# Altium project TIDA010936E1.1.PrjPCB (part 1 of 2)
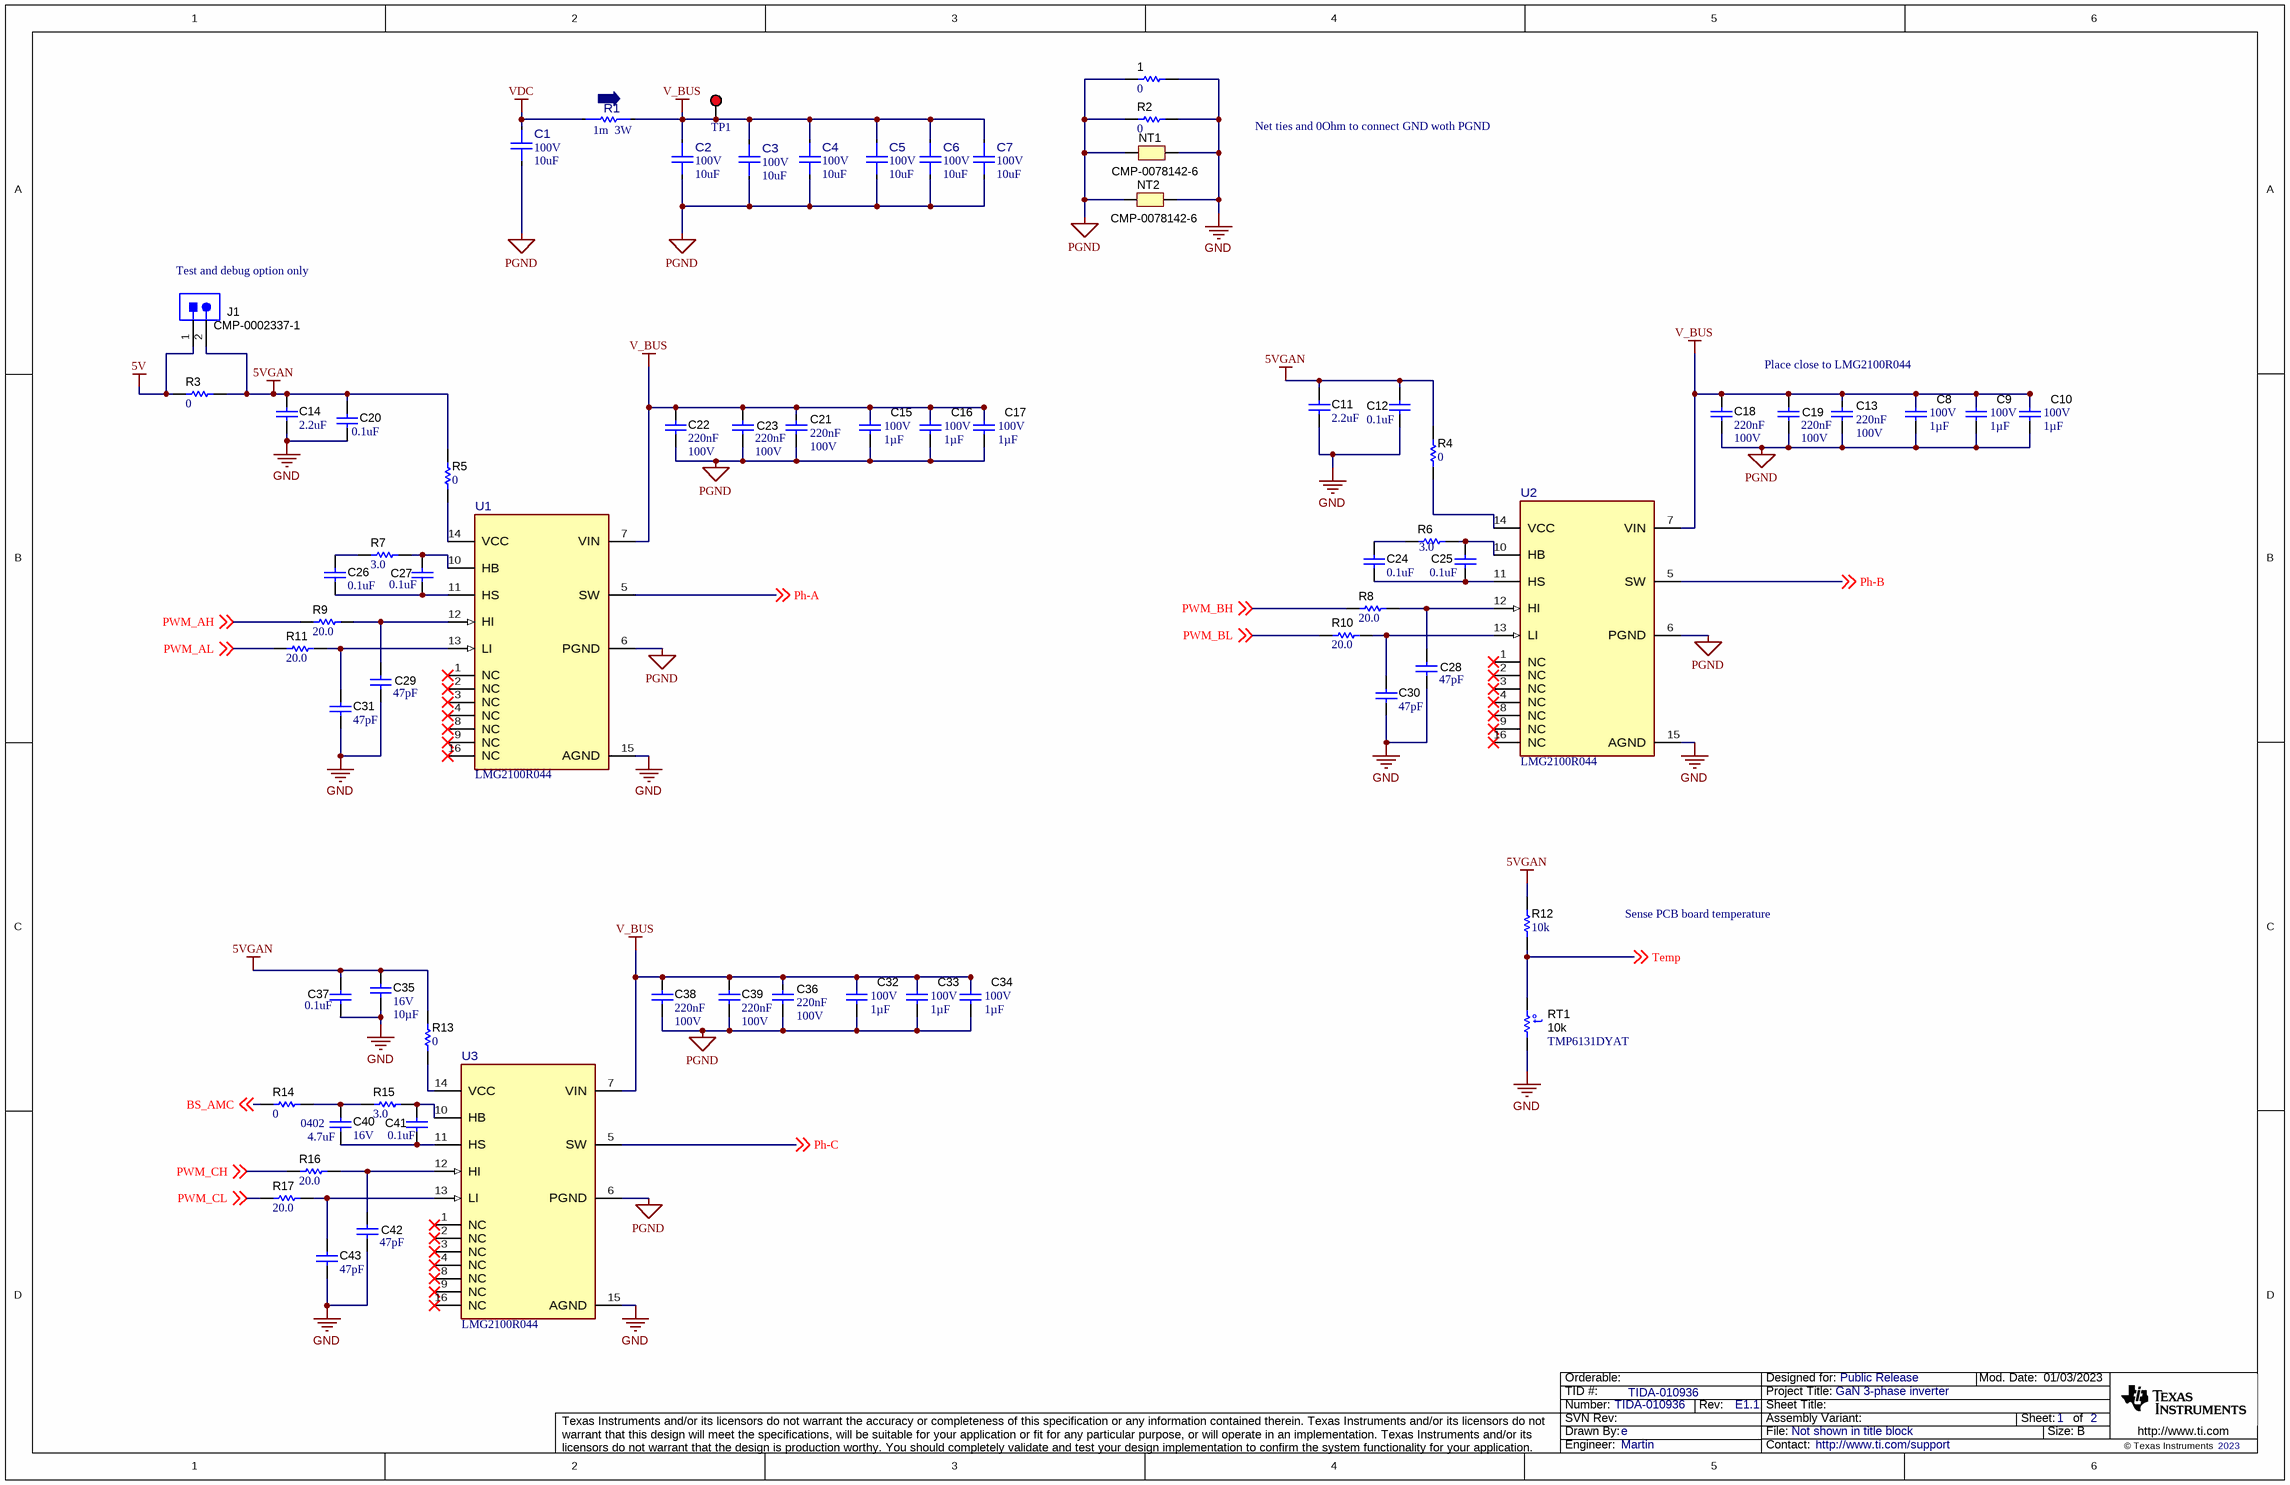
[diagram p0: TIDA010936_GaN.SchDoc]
CopyrightYear: 2023; PCB_Layout: Eason; PCB_Rev: E1.1; PRJ_Customer: Public Release; PRJ_Engineer: Martin; PRJ_Number: TIDA-010936; PRJ_Title: GaN 3-phase inverter; SCH_Rev: E1.1; TechSupport: http://www.ti.com/support; TID: TIDA-010936
5 sheets, 225 parts. Net scope: global (net labels, ports and power ports of the same name join across sheets).
Board file: TIDA010936.PcbDoc
Sheets:
  TIDA010936_GaN.SchDoc
  TIDA010936_Current sensing.SchDoc
  TIDA010936_Interface.SchDoc
  TIDA010936_Power.SchDoc
  TIDA010936_GaN_Hardware.SchDoc

## Sheet TIDA010936_GaN.SchDoc
size 431 x 279 mm; Date: Not shown in title block; ApprovedBy: Not shown in title block; CheckedBy: Not shown in title block; Author: Not shown in title block; CompanyName: Not shown in title block; DrawnBy: e; Engineer: Not shown in title block; Organization: Not shown in title block; Address1: Not shown in title block; Address2: Not shown in title block; Address3: Not shown in title block; Address4: Not shown in title block; DocumentNumber: 2; Revision: Use project parameter SCH_Rev; SheetNumber: 1; SheetTotal: 2; PageSetup: Record=PageOptions¦CenterHorizontal=True¦CenterVertical=True¦PrintScale=1.00¦XCorrection=1.00¦YCorrection=1.00¦PrintKind=0¦BorderSize=5000000¦LeftOffset=0¦BottomOffset=0¦Orientation=2¦PaperLength=1000¦PaperWidth=1000¦Scale=100¦PaperSource=15¦PrintQuality=600¦MediaType=1¦DitherType=10¦PaperKind=Letter¦PrintScaleMode=1

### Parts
1  ValueDisplayed: 0  [0603]  (hidden comment: CMP-0025883-3)
C1  VDC_V: 100V  ValueDisplayed: 10uF  [FP-C3225X7R2A106K250AC_1210-MFG]  (hidden comment: C3225X7R2A106K250AC)
C2  VDC_V: 100V  ValueDisplayed: 10uF  [FP-C3225X7R2A106K250AC_1210-MFG]  (hidden comment: C3225X7R2A106K250AC)
C3  VDC_V: 100V  ValueDisplayed: 10uF  [FP-C3225X7R2A106K250AC_1210-MFG]  (hidden comment: C3225X7R2A106K250AC)
C4  VDC_V: 100V  ValueDisplayed: 10uF  [FP-C3225X7R2A106K250AC_1210-MFG]  (hidden comment: C3225X7R2A106K250AC)
C5  VDC_V: 100V  ValueDisplayed: 10uF  [FP-C3225X7R2A106K250AC_1210-MFG]  (hidden comment: C3225X7R2A106K250AC)
C6  VDC_V: 100V  ValueDisplayed: 10uF  [FP-C3225X7R2A106K250AC_1210-MFG]  (hidden comment: C3225X7R2A106K250AC)
C7  VDC_V: 100V  ValueDisplayed: 10uF  [FP-C3225X7R2A106K250AC_1210-MFG]  (hidden comment: C3225X7R2A106K250AC)
C8  VDC_V: 100V  ValueDisplayed: 1µF  [0805_HV]  (hidden comment: C2012X7S2A105K125AE)
C9  VDC_V: 100V  ValueDisplayed: 1µF  [0805_HV]  (hidden comment: C2012X7S2A105K125AE)
C10  VDC_V: 100V  ValueDisplayed: 1µF  [0805_HV]  (hidden comment: C2012X7S2A105K125AE)
C11  ValueDisplayed: 2.2uF  [0402_065]  (hidden comment: C1005X7S1A225K050BC)
C12  ValueDisplayed: 0.1uF  [0402]  (hidden comment: CMP-0006351-2)
C13  Cap_F: 220nF  VDC_V: 100V  [0603]  (hidden comment: HMK107C7224KAHTE)
C14  ValueDisplayed: 2.2uF  [0402_065]  (hidden comment: C1005X7S1A225K050BC)
C15  VDC_V: 100V  ValueDisplayed: 1µF  [0805_HV]  (hidden comment: C2012X7S2A105K125AE)
C16  VDC_V: 100V  ValueDisplayed: 1µF  [0805_HV]  (hidden comment: C2012X7S2A105K125AE)
C17  VDC_V: 100V  ValueDisplayed: 1µF  [0805_HV]  (hidden comment: C2012X7S2A105K125AE)
C18  Cap_F: 220nF  VDC_V: 100V  [0603]  (hidden comment: HMK107C7224KAHTE)
C19  Cap_F: 220nF  VDC_V: 100V  [0603]  (hidden comment: HMK107C7224KAHTE)
C20  ValueDisplayed: 0.1uF  [0402]  (hidden comment: CMP-0006351-2)
C21  Cap_F: 220nF  VDC_V: 100V  [0603]  (hidden comment: HMK107C7224KAHTE)
C22  Cap_F: 220nF  VDC_V: 100V  [0603]  (hidden comment: HMK107C7224KAHTE)
C23  Cap_F: 220nF  VDC_V: 100V  [0603]  (hidden comment: HMK107C7224KAHTE)
C24  ValueDisplayed: 0.1uF  [0402]  (hidden comment: CMP-0006351-2)
C25  ValueDisplayed: 0.1uF  [0402]  (hidden comment: CMP-0006351-2)
C26  ValueDisplayed: 0.1uF  [0402]  (hidden comment: CMP-0006351-2)
C27  ValueDisplayed: 0.1uF  [0402]  (hidden comment: CMP-0006351-2)
C28  ValueDisplayed: 47pF  [0402]  (hidden comment: CMP-0006388-2)
C29  ValueDisplayed: 47pF  [0402]  (hidden comment: CMP-0006388-2)
C30  ValueDisplayed: 47pF  [0402]  (hidden comment: CMP-0006388-2)
C31  ValueDisplayed: 47pF  [0402]  (hidden comment: CMP-0006388-2)
C32  VDC_V: 100V  ValueDisplayed: 1µF  [0805_HV]  (hidden comment: C2012X7S2A105K125AE)
C33  VDC_V: 100V  ValueDisplayed: 1µF  [0805_HV]  (hidden comment: C2012X7S2A105K125AE)
C34  VDC_V: 100V  ValueDisplayed: 1µF  [0805_HV]  (hidden comment: C2012X7S2A105K125AE)
C35  VDC_V: 16V  ValueDisplayed: 10µF  [0603]  (hidden comment: GRM188C81C106MA73D)
C36  Cap_F: 220nF  VDC_V: 100V  [0603]  (hidden comment: HMK107C7224KAHTE)
C37  ValueDisplayed: 0.1uF  [0402]  (hidden comment: CMP-0006351-2)
C38  Cap_F: 220nF  VDC_V: 100V  [0603]  (hidden comment: HMK107C7224KAHTE)
C39  Cap_F: 220nF  VDC_V: 100V  [0603]  (hidden comment: HMK107C7224KAHTE)
C40  PackageReference: 0402  VDC_V: 16V  ValueDisplayed: 4.7uF  [0402_070]  (hidden comment: GRM155D81C475ME15D)
C41  ValueDisplayed: 0.1uF  [0402]  (hidden comment: CMP-0006351-2)
C42  ValueDisplayed: 47pF  [0402]  (hidden comment: CMP-0006388-2)
C43  ValueDisplayed: 47pF  [0402]  (hidden comment: CMP-0006388-2)
J1  CMP-0002337-1  [CONN_PEC02SAAN]
NT1  CMP-0078142-6  [Net-Tie_50milWide_30milLong]  (net tie, no BOM)
NT2  CMP-0078142-6  [Net-Tie_50milWide_30milLong]  (net tie, no BOM)
R1  value 1m  Power_W: 3W  [FP-ULRG32512R001FLFSLT_2512-MFG]  (hidden comment: ULRG32512R001FLFSLT)
R2  ValueDisplayed: 0  [0603]  (hidden comment: CMP-0025883-3)
R3  ValueDisplayed: 0  [0402]  (hidden comment: CMP-0026822-3)
R4  ValueDisplayed: 0  [0402]  (hidden comment: CMP-0026822-3)
R5  ValueDisplayed: 0  [0402]  (hidden comment: CMP-0026822-3)
R6  ValueDisplayed: 3.0  [0402]  (hidden comment: CRCW04023R00JNED)
R7  ValueDisplayed: 3.0  [0402]  (hidden comment: CRCW04023R00JNED)
R8  ValueDisplayed: 20.0  [0402]  (hidden comment: CMP-0026164-2)
R9  ValueDisplayed: 20.0  [0402]  (hidden comment: CMP-0026164-2)
R10  ValueDisplayed: 20.0  [0402]  (hidden comment: CMP-0026164-2)
R11  ValueDisplayed: 20.0  [0402]  (hidden comment: CMP-0026164-2)
R12  ValueDisplayed: 10k  [0402]  (hidden comment: CMP-0026825-5)
R13  ValueDisplayed: 0  [0402]  (hidden comment: CMP-0026822-3)
R14  ValueDisplayed: 0  [0402]  (hidden comment: CMP-0026822-3)
R15  ValueDisplayed: 3.0  [0402]  (hidden comment: CRCW04023R00JNED)
R16  ValueDisplayed: 20.0  [0402]  (hidden comment: CMP-0026164-2)
R17  ValueDisplayed: 20.0  [0402]  (hidden comment: CMP-0026164-2)
RT1  value 10k  [DYA0002A-MFG]  (hidden comment: TMP6131DYAT)
TP1  5000  [Keystone5000]  (value not drawn)
U1  LMG2100R044  [RAR0016A-MFG]
U2  LMG2100R044  [RAR0016A-MFG]
U3  LMG2100R044  [RAR0016A-MFG]

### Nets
5V: J1.1 R3.1
5VGAN: C11.1 C12.2 C14.1 C20.1 C35.1 C37.2 J1.2 R3.2 R4.2 R5.2 R12.2 R13.2
GND: 1.2 C11.2 C12.1 C14.2 C20.2 C28.2 C29.2 C30.2 C31.2 C35.2 C37.1 C42.2 C43.2 NT1.2 NT2.2 R2.2 RT1.1 U1.15(AGND) U2.15(AGND) U3.15(AGND)
PGND: 1.1 C1.2 C2.2 C3.1 C4.2 C5.2 C6.2 C7.2 C8.2 C9.2 C10.2 C13.2 C15.2 C16.2 C17.2 C18.2 C19.2 C21.2 C22.2 C23.2 C32.2 C33.2 C34.2 C36.2 C38.2 C39.2 NT1.1 NT2.1 R2.1 U1.6(PGND) U2.6(PGND) U3.6(PGND)
Ph-A: U1.5(SW) ; off-sheet Ph-A  [project net AIN+]
Ph-B: U2.5(SW) ; off-sheet Ph-B  [project net BIN+]
Ph-C: U3.5(SW) ; off-sheet Ph-C  [project net AMC_GND]
V_BUS: C2.1 C3.2 C4.1 C5.1 C6.1 C7.1 C8.1 C9.1 C10.1 C13.1 C15.1 C16.1 C17.1 C18.1 C19.1 C21.1 C22.1 C23.1 C32.1 C33.1 C34.1 C36.1 C38.1 C39.1 R1.2 TP1.1 U1.7(VIN) U2.7(VIN) U3.7(VIN)
VDC: C1.1 R1.1
BS_AMC: R14.2 ; off-sheet BS_AMC
PWM_AH: R9.2 ; off-sheet PWM_AH
PWM_AL: R11.2 ; off-sheet PWM_AL
PWM_BH: R8.2 ; off-sheet PWM_BH
PWM_BL: R10.2 ; off-sheet PWM_BL
PWM_CH: R16.2 ; off-sheet PWM_CH
PWM_CL: R17.2 ; off-sheet PWM_CL
Temp: R12.1 RT1.2 ; off-sheet Temp
NetC24_1: C24.1 R6.1
NetC24_2: C24.2 C25.2 U2.11(HS)
NetC25_1: C25.1 R6.2 U2.10(HB)
NetC26_1: C26.1 R7.1
NetC26_2: C26.2 C27.2 U1.11(HS)
NetC27_1: C27.1 R7.2 U1.10(HB)
NetC28_1: C28.1 R8.1 U2.12(HI)
NetC29_1: C29.1 R9.1 U1.12(HI)
NetC30_1: C30.1 R10.1 U2.13(LI)
NetC31_1: C31.1 R11.1 U1.13(LI)
NetC40_1: C40.1 R14.1 R15.1
NetC40_2: C40.2 C41.2 U3.11(HS)
NetC41_1: C41.1 R15.2 U3.10(HB)
NetC42_1: C42.1 R16.1 U3.12(HI)
NetC43_1: C43.1 R17.1 U3.13(LI)
NetR4_1: R4.1 U2.14(VCC)
NetR5_1: R5.1 U1.14(VCC)
NetR13_1: R13.1 U3.14(VCC)

Not connected (* = marked no-connect by the designer): U1 1(NC)* 2(NC)* 3(NC)* 4(NC)* 8(NC)* 9(NC)* 16(NC)*; U2 1(NC)* 2(NC)* 3(NC)* 4(NC)* 8(NC)* 9(NC)* 16(NC)*; U3 1(NC)* 2(NC)* 3(NC)* 4(NC)* 8(NC)* 9(NC)* 16(NC)*

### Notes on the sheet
- (near R1) ⬅
- Net ties and 0Ohm to connect GND woth PGND
- (near J1) Test and debug option only
- Place close to LMG2100R044
- Sense PCB board temperature

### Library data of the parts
1 R2 = CMP-0025883-3: RES, 0, 5%, 0.1 W, 0603; PartNumber: MCR03EZPJ000; Manufacturer: Rohm; Value: 0; Value_Code: 0000; Power_W: 100mW; Value2: 0.1W; VDC_V: 50V; TempCo: 400 ppm/C; SizeArea_mm2: 1.28; SizeX_mm: 1.6; SizeY_mm: 0.8; SizeZ_mm: 1; EIA_Code: E24; U/M: EA; AEC Category: Q200; AEC Qualified: N
C1-C7 = CMP-0096021-1: 10 µF ±10% 100V Ceramic Capacitor X7R 1210 (3225 Metric); Manufacturer: TDK; Cap_F: 10µF; AEC Qualified: No; Value: 10µF; SizeZ_mm: 2.85mm; TempCo: 15%
C8-C10 C15-C17 C32-C34 = CMP-0750059-1: CAP, CERM, 1 µF, 100 V,+/- 10%, X7S, 0805; Manufacturer: TDK; TaMax_C: 125°C; SizeAreaWB_mm2: 6.75; SizeY_mm: 1.25; Green_REACh: Incomplete; TaMin_C: -55°C; Cap_Case: 0805; SizeZ_mm: 1.45; U/M: EA; SizeX_mm: 2; Polarized: N; Green_Lifecycle: Active; SizeArea_mm2: 2.5; Value: 1uF; AEC Category: Q200
C11 C14 = CMP-0006302-2: CAP, CERM, 2.2 uF, 10 V, +/- 10%, X7S, 0402; Manufacturer: TDK; Polarized: N; Value: 2.2uF; U/M: EA; Cap_F: 2.2µF; ESR_ohm: 5.925m; Value1: 0.005925 ohm; VDC_V: 10V; IRMS_A: 2.0559A; TaMin_C: -55°C; TaMax_C: 125°C; SizeArea_mm2: 0.5; SizeAreaWB_mm2: 3; SizeX_mm: 1; SizeZ_mm: 0.65; AEC Category: Q200
C12 C20 C24-C27 C37 C41 = CMP-0006351-2: CAP, CERM, 0.1 uF, 16 V, +/- 10%, X7R, 0402; PartNumber: GCM155R71C104KA55D; Manufacturer: MuRata; Polarized: N; Value: 0.1uF; U/M: EA; Cap_F: 100nF; Value1: Unknown; VDC_V: 16V; TaMin_C: -55°C; TaMax_C: 125°C; AEC Category: Q200; SizeAreaWB_mm2: 3; SizeZ_mm: 0.6; SizeX_mm: 1; SizeY_mm: 0.5
C13 C18 C19 C21-C23 C36 C38 C39 = CMP-0077894-3: CAP, CERM, 0.22 µF, 100 V,+/- 10%, X7S, AEC-Q200 Grade 1, 0603; Manufacturer: Taiyo Yuden; TaMin_C: -55°C; Polarized: N; SizeAreaWB_mm2: 4.68; U/M: EA; Value: 0.22uF; TaMax_C: 125°C; SizeZ_mm: 1.0; SizeX_mm: 1.6; SizeY_mm: 0.8; SizeArea_mm2: 1.28; AEC Qualified: Y; AEC Category: Q200; ValueDisplayed: 0.22µF; AEC Grade: 1
C28-C31 C42 C43 = CMP-0006388-2: CAP, CERM, 47 pF, 25 V, +/- 5%, C0G/NP0, 0402; PartNumber: GRM1555C1E470JA01D; Manufacturer: MuRata; Polarized: N; Value: 47pF; U/M: EA; Value1: Unknown; VDC_V: 25V; TaMin_C: -55°C; TaMax_C: 125°C; AEC Category: Q200; SizeAreaWB_mm2: 3; SizeZ_mm: 0.6; SizeX_mm: 1; SizeY_mm: 0.5
C35 = CMP-0086062-1: CAP, CERM, 10 µF, 16 V,+/- 20%, X6S, 0603; Manufacturer: MuRata; U/M: EA; AEC Category: Q200; SizeX_mm: 1.6; SizeY_mm: 0.8; SizeZ_mm: 1; Value: 10uF; SizeArea_mm2: 1.28; TaMin_C: -55°C; Polarized: N; SizeAreaWB_mm2: 4.68; TaMax_C: 105°C
C40 = CMP-0006527-2: CAP, CERM, 4.7 uF, 16 V, +/- 20%, X6T, 0402; Manufacturer: MuRata; TaMin_C: -55°C; Polarized: N; SizeAreaWB_mm2: 3; Value1: Unknown; U/M: EA; Value: 4.7uF; TaMax_C: 105°C; SizeZ_mm: 0.7; SizeX_mm: 1; SizeY_mm: 0.5; Cap_F: 4.7µF; AEC Category: Q200
J1 = CMP-0002337-1: Header, 100mil, 2x1, Tin, TH; PartNumber: PEC02SAAN; Manufacturer: Sullins Connector Solutions; Pitch_mm: 2.54; Gender: Male; Shrouded: N; Row_Count: 1; Current_A: 3A; Voltage_V: 1.8kV; Cert_UL: Y; CNHeader: TRUE; Green_Lifecycle: Not Set; Green_REACh: Incomplete; CT: FALSE
NT1 NT2 = CMP-0078142-6: Single point connection between nets.
R1 = CMP-0042666-1: Res Metal Strip 2512 0.001 Ohm 1% 3W ±50ppm/C Pad SMD Automotive T/R; Manufacturer: TT Electronics; AEC Grade: Grade 0; AEC Qualified: Yes; SizeZ_mm: 0.8mm; TempCo: 50ppm/°C; TaMax_C: +170°C; TaMin_C: -55°C
R3-R5 R13 R14 = CMP-0026822-3: RES, 0, 5%, 0.063 W, AEC-Q200 Grade 0, 0402; PartNumber: CRCW04020000Z0ED; Manufacturer: Vishay-Dale; Value: 0; Value_Code: 0000; Power_W: 63mW; Value2: 0.063W; VDC_V: 50V; TempCo: 200 ppm/C; SizeArea_mm2: 0.5; SizeX_mm: 1; SizeZ_mm: 0.6; EIA_Code: E24; AEC Category: Q200; AEC Qualified: Y
R6 R7 R15 = CMP-0026925-3: RES, 3.0, 5%, 0.063 W, AEC-Q200 Grade 0, 0402; Manufacturer: Vishay-Dale; Power_W: 63mW; TempCo: 200 ppm/C; Value_Code: 3R00; Value: 3.0; EIA_Code: E24; Res_ohm: 3; SizeX_mm: 1; SizeY_mm: 0.5; SizeZ_mm: 0.6; Value2: 0.063W; AEC Qualified: Y; VDC_V: 50V; AEC Category: Q200; AEC Grade: 0
R8-R11 R16 R17 = CMP-0026164-2: RES, 20.0, 1%, 0.063 W, AEC-Q200 Grade 0, 0402; PartNumber: CRCW040220R0FKED; Manufacturer: Vishay-Dale; Value: 20.0; Res_ohm: 20; Value_Code: 20R0; Power_W: 63mW; Value2: 0.063W; VDC_V: 50V; TempCo: 100 ppm/C; EIA_Code: E96; AEC Category: Q200; AEC Qualified: Y; AEC Grade: 0; SizeX_mm: 1; SizeY_mm: 0.5; SizeZ_mm: 0.6
R12 = CMP-0026825-5: RES, 10 k, 5%, 0.063 W, AEC-Q200 Grade 0, 0402; PartNumber: CRCW040210K0JNED; Manufacturer: Vishay-Dale; Value: 10k; Value_Code: 10k0; Power_W: 63mW; Value2: 0.063W; VDC_V: 50V; TempCo: 200 ppm/C; SizeArea_mm2: 0.5; SizeX_mm: 1; SizeZ_mm: 0.6; EIA_Code: E24; AEC Category: Q200; AEC Qualified: Y; AEC Grade: 0
RT1 = CMP-0091865-2: ±1% tolerance 10kΩ linear thermistor available in 0402 and 0603 package options 2-SOT-5X3 -40 to 125; Manufacturer: Texas Instruments; Max Current: 400uA; AEC Qualified: No; TJmax_C: +155°C; TaMin_C: -40°C; TempCo: 6400ppm/°C; TaMax_C: +125°C; VDC_V: 5.5V; SizeZ_mm: 0.77mm; AEC Category: Q200; CompType: IC
TP1 = CMP-0055137-1: Test Point, Miniature, Red, TH; Manufacturer: Keystone; CNHeader: FALSE; Green_Lifecycle: Active; Green_REACh: Passed; ContactFinish: Silver; CT: TRUE
U1-U3 = CMP-0097820-2: Manufacturer: Texas Instruments; AEC Category: Q200; CompType: IC; Standoff Height: 0mm; SizeZ_mm: 0.89mm

## Sheet TIDA010936_Current sensing.SchDoc
size 431 x 279 mm; Date: Not shown in title block; ApprovedBy: Not shown in title block; CheckedBy: Not shown in title block; Author: Not shown in title block; CompanyName: Not shown in title block; Engineer: Not shown in title block; Organization: Not shown in title block; Address1: Not shown in title block; Address2: Not shown in title block; Address3: Not shown in title block; Address4: Not shown in title block; DocumentNumber: 2; Revision: Use project parameter SCH_Rev; SheetNumber: 2; SheetTotal: 3; PageSetup: Record=PageOptions¦CenterHorizontal=True¦CenterVertical=True¦PrintScale=1.00¦XCorrection=1.00¦YCorrection=1.00¦PrintKind=0¦BorderSize=5000000¦LeftOffset=0¦BottomOffset=0¦Orientation=2¦PaperLength=1000¦PaperWidth=1000¦Scale=100¦PaperSource=15¦PrintQuality=600¦MediaType=1¦DitherType=10¦PaperKind=Letter¦PrintScaleMode=1
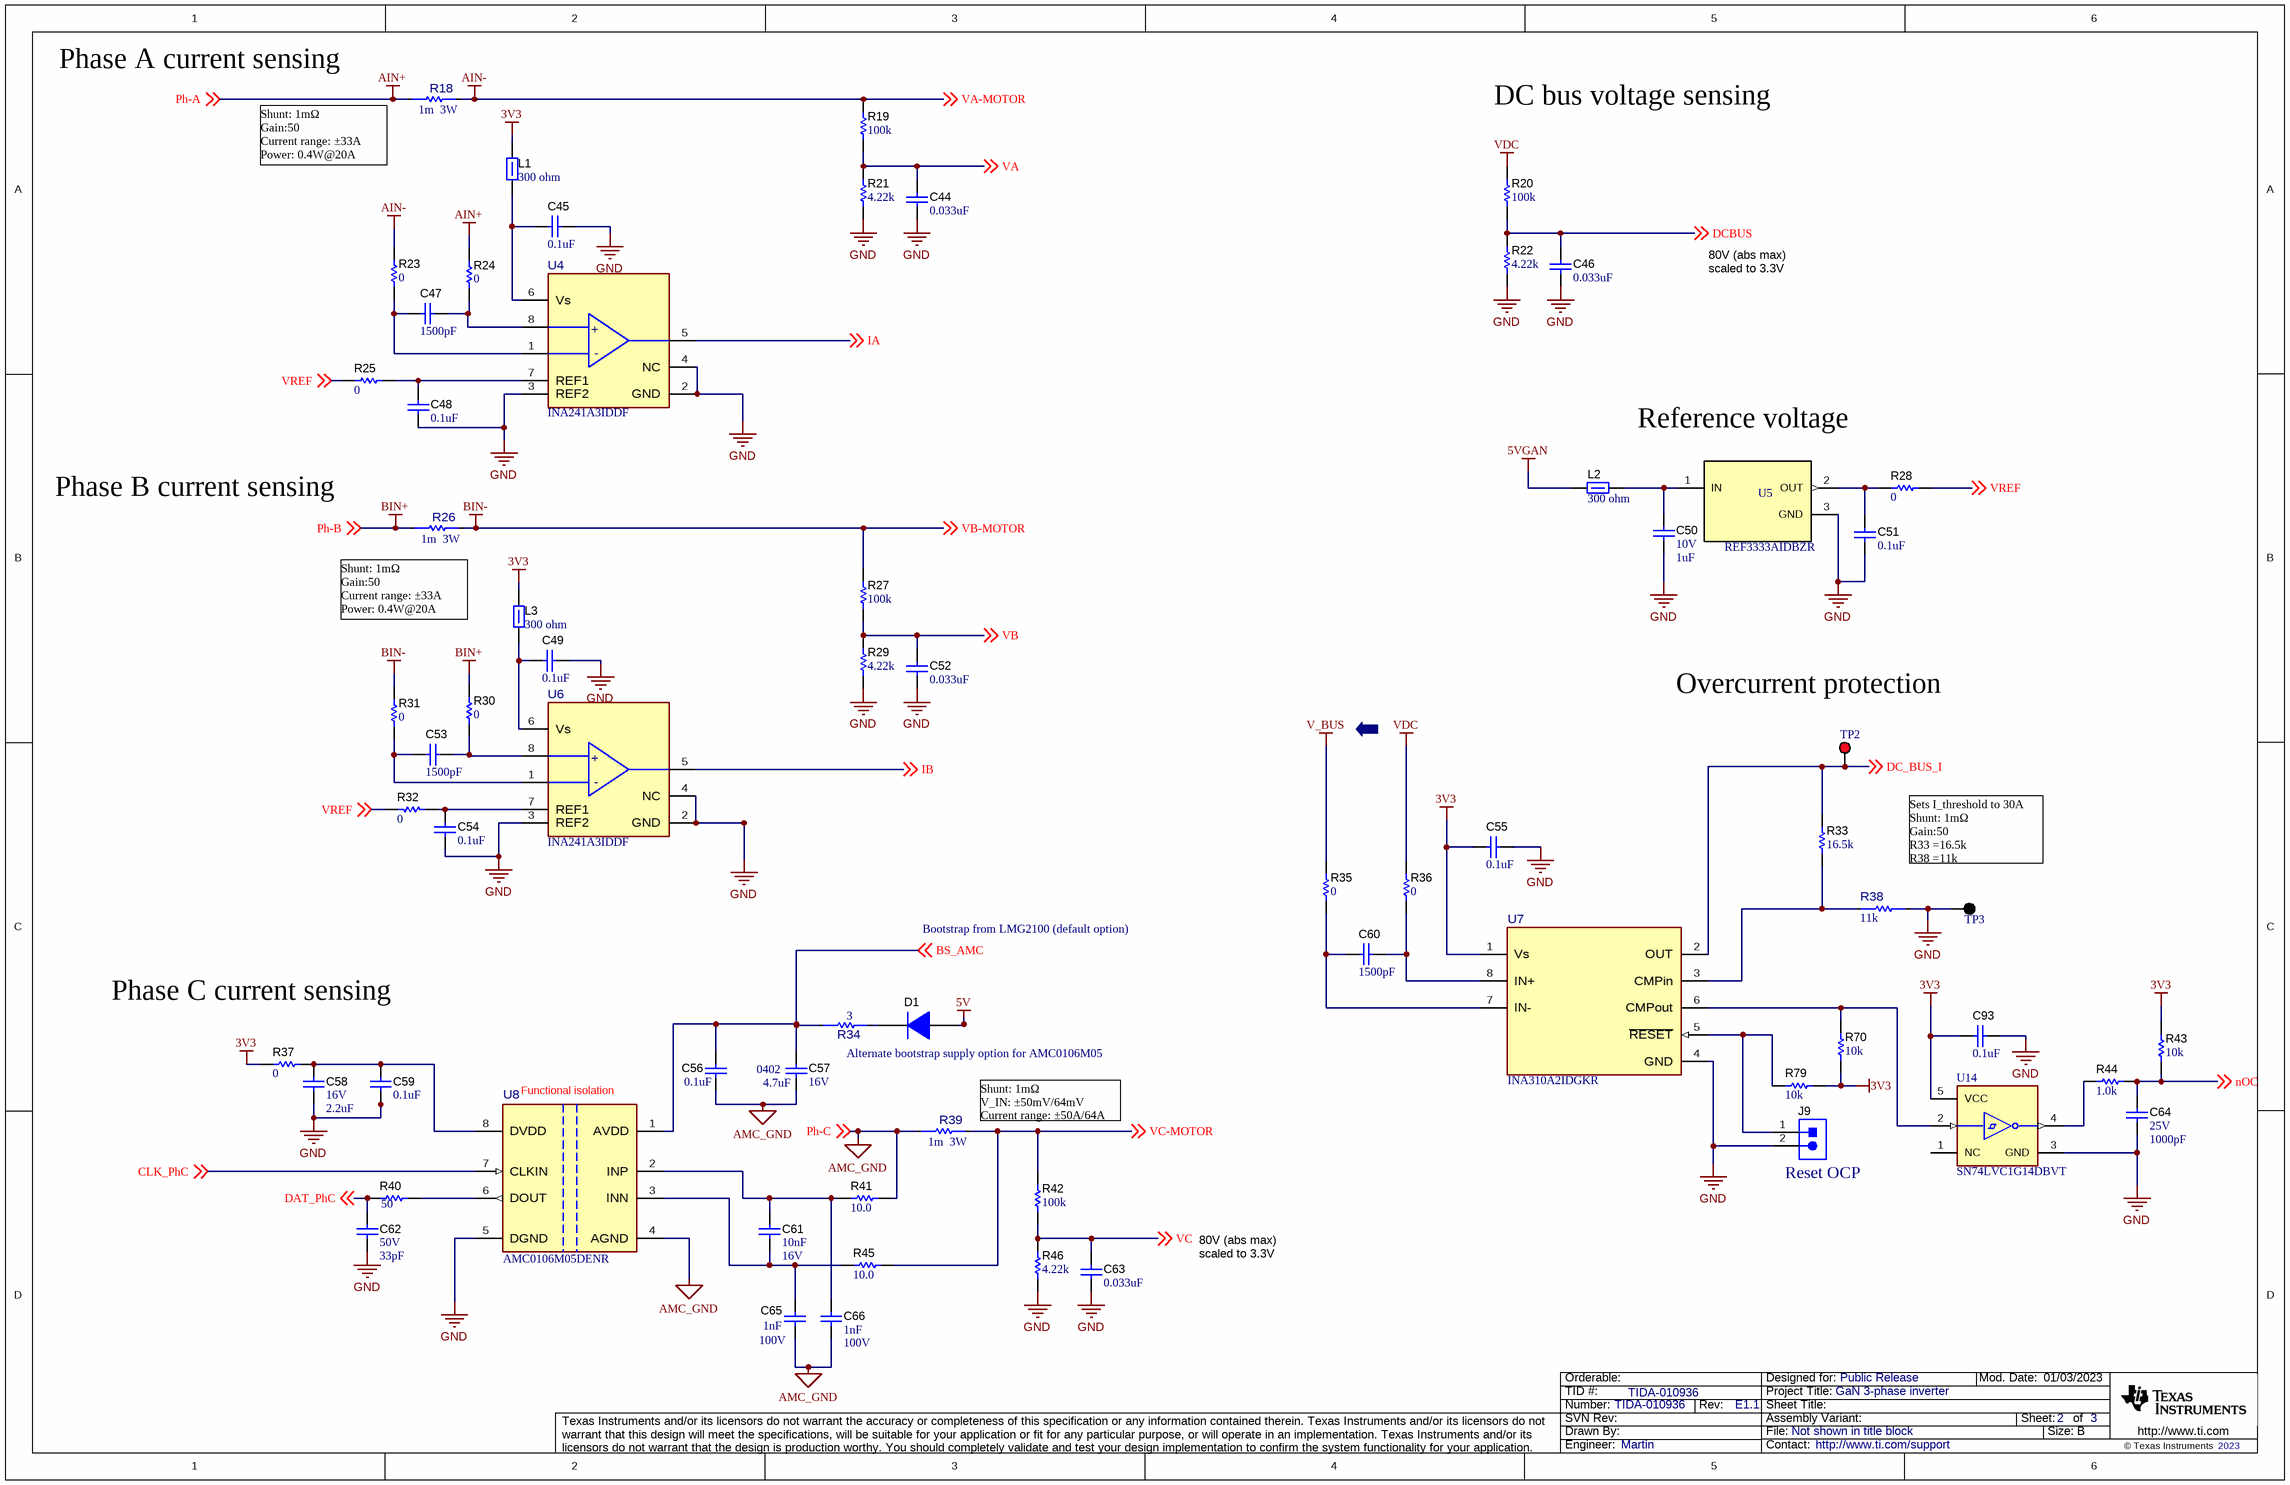
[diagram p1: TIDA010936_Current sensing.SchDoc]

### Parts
C44  ValueDisplayed: 0.033uF  [0402]  (hidden comment: CMP-0006632-2)
C45  ValueDisplayed: 0.1uF  [0402]  (hidden comment: CMP-0006351-2)
C46  ValueDisplayed: 0.033uF  [0402]  (hidden comment: CMP-0006632-2)
C47  ValueDisplayed: 1500pF  [0402]  (hidden comment: CMP-0006245-2)
C48  ValueDisplayed: 0.1uF  [0603]  (hidden comment: CMP-0007378-5)
C49  ValueDisplayed: 0.1uF  [0402]  (hidden comment: CMP-0006351-2)
C50  VDC_V: 10V  ValueDisplayed: 1uF  [0603]  (hidden comment: GRM188R61A105KA61D)
C51  ValueDisplayed: 0.1uF  [0603]  (hidden comment: CMP-0007378-5)
C52  ValueDisplayed: 0.033uF  [0402]  (hidden comment: CMP-0006632-2)
C53  ValueDisplayed: 1500pF  [0402]  (hidden comment: CMP-0006245-2)
C54  ValueDisplayed: 0.1uF  [0603]  (hidden comment: CMP-0007378-5)
C55  ValueDisplayed: 0.1uF  [0402]  (hidden comment: CMP-0006351-2)
C56  ValueDisplayed: 0.1uF  [0402]  (hidden comment: CMP-0006351-2)
C57  PackageReference: 0402  VDC_V: 16V  ValueDisplayed: 4.7uF  [0402_070]  (hidden comment: GRM155D81C475ME15D)
C58  VDC_V: 16V  ValueDisplayed: 2.2uF  [0402]  (hidden comment: GRM155R61C225KE11D)
C59  ValueDisplayed: 0.1uF  [0402]  (hidden comment: CMP-0006351-2)
C60  ValueDisplayed: 1500pF  [0402]  (hidden comment: CMP-0006245-2)
C61  Cap_F: 10nF  VDC_V: 16V  [0603]  (hidden comment: 885012206040)
C62  VDC_V: 50V  ValueDisplayed: 33pF  [0603]  (hidden comment: C0603C330J5GACTU)
C63  ValueDisplayed: 0.033uF  [0402]  (hidden comment: CMP-0006632-2)
C64  VDC_V: 25V  ValueDisplayed: 1000pF  [0603]  (hidden comment: C0603C102F3GACTU)
C65  Cap_F: 1nF  VDC_V: 100V  [0603]  (hidden comment: 06031C102JAT2A)
C66  Cap_F: 1nF  VDC_V: 100V  [0603]  (hidden comment: 06031C102JAT2A)
C93  ValueDisplayed: 0.1uF  [0402]  (hidden comment: CMP-0006351-2)
D1  ES1C-13-F;  Superfast Rectifier, 150 V, 1 A  [SMA]  (value not drawn)
J9  (no value)  [CONN_PEC02SAAN]
L1  value 300 ohm  [0402]  (hidden comment: CMP-0003227-1)
L2  value 300 ohm  [0402]  (hidden comment: CMP-0003227-1)
L3  value 300 ohm  [0402]  (hidden comment: CMP-0003227-1)
R18  value 1m  Power_W: 3W  [FP-ULRG32512R001FLFSLT_2512-MFG]  (hidden comment: ULRG32512R001FLFSLT)
R19  ValueDisplayed: 100k  [0402]  (hidden comment: CMP-0025950-3)
R20  ValueDisplayed: 100k  [0402]  (hidden comment: CMP-0025950-3)
R21  ValueDisplayed: 4.22k  [0402]  (hidden comment: CMP-0026407-2)
R22  ValueDisplayed: 4.22k  [0402]  (hidden comment: CMP-0026407-2)
R23  ValueDisplayed: 0  [0402]  (hidden comment: CMP-0026822-3)
R24  ValueDisplayed: 0  [0402]  (hidden comment: CMP-0026822-3)
R25  ValueDisplayed: 0  [0402]  (hidden comment: CMP-0026822-3)
R26  value 1m  Power_W: 3W  [FP-ULRG32512R001FLFSLT_2512-MFG]  (hidden comment: ULRG32512R001FLFSLT)
R27  ValueDisplayed: 100k  [0402]  (hidden comment: CMP-0025950-3)
R28  ValueDisplayed: 0  [0402]  (hidden comment: CMP-0026822-3)
R29  ValueDisplayed: 4.22k  [0402]  (hidden comment: CMP-0026407-2)
R30  ValueDisplayed: 0  [0402]  (hidden comment: CMP-0026822-3)
R31  ValueDisplayed: 0  [0402]  (hidden comment: CMP-0026822-3)
R32  ValueDisplayed: 0  [0402]  (hidden comment: CMP-0026822-3)
R33  ValueDisplayed: 16.5k  [0402]  (hidden comment: CRCW040216K5FKED)
R34  value 3  [FP-CRCW06033R00FKEAHP_0603-MFG]  (hidden comment: CRCW06033R00FKEAHP)
R35  ValueDisplayed: 0  [0402]  (hidden comment: CMP-0026822-3)
R36  ValueDisplayed: 0  [0402]  (hidden comment: CMP-0026822-3)
R37  ValueDisplayed: 0  [0402]  (hidden comment: CMP-0026822-3)
R38  value 11k  [FP-RMCF0402FT11K0_0402-MFG]  (hidden comment: RMCF0402FT11K0)
R39  value 1m  Power_W: 3W  [FP-ULRG32512R001FLFSLT_2512-MFG]  (hidden comment: ULRG32512R001FLFSLT)
R40  ValueDisplayed: 50  [0603]  (hidden comment: CRCW060350R0FKEA)
R41  ValueDisplayed: 10.0  [0603]  (hidden comment: CRCW060310R0FKEAHP)
R42  ValueDisplayed: 100k  [0402]  (hidden comment: CMP-0025950-3)
R43  ValueDisplayed: 10k  [0402]  (hidden comment: CMP-0026825-5)
R44  ValueDisplayed: 1.0k  [0603]  (hidden comment: RC0603JR-071KL)
R45  ValueDisplayed: 10.0  [0603]  (hidden comment: CRCW060310R0FKEAHP)
R46  ValueDisplayed: 4.22k  [0402]  (hidden comment: CMP-0026407-2)
R70  ValueDisplayed: 10k  [0402]  (hidden comment: CMP-0026825-5)
R79  ValueDisplayed: 10k  [0402]  (hidden comment: CMP-0026825-5)
TP2  5000  [Keystone5000]  (value not drawn)
TP3  CMP-0055138-2  [Keystone5001]  (value not drawn)
U4  INA241A3IDDF  [DDF0008A-MFG]
U5  REF3333AIDBZR  [DBZ0003A_N]
U6  INA241A3IDDF  [DDF0008A-MFG]
U7  INA310A2IDGKR  [DGK0008A-MFG]
U8  AMC0106M05DENR  [DEN0008A-MFG-NO_VIA]
U14  SN74LVC1G14DBVT  [FP-DBV0005A-MFG]

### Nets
3V3: C55.2 C93.1 L1.1 L3.1 R37.2 R43.2 R70.2 R79.1 U7.1(Vs) U14.5(VCC)
5V: D1.2(A)
5VGAN: L2.2
AIN+: R18.1 R24.2 ; off-sheet Ph-A  [also labelled Ph-A]
AIN-: R18.2 R19.2 R23.2 ; off-sheet VA-MOTOR  [also labelled VA-MOTOR]
AMC_GND: C56.2 C57.2 C65.2 C66.2 R39.1 R41.2 U8.4(AGND) ; off-sheet Ph-C  [also labelled Ph-C]
BIN+: R26.1 R30.2 ; off-sheet Ph-B  [also labelled Ph-B]
BIN-: R26.2 R27.2 R31.2 ; off-sheet VB-MOTOR  [also labelled VB-MOTOR]
GND: C44.2 C45.1 C46.2 C48.1 C49.1 C50.2 C51.1 C52.2 C54.1 C55.1 C58.2 C59.2 C62.2 C63.2 C64.2 C93.2 J9.2 R21.1 R22.1 R29.1 R38.2 R46.1 TP3.1 U4.2(GND) U4.3(REF2) U4.4(NC) U5.3(GND) U6.2(GND) U6.3(REF2) U6.4(NC) U7.4(GND) U8.5(DGND) U14.3(GND)
V_BUS: R35.2
VDC: R20.2 R36.2
BS_AMC: C56.1 C57.1 R34.1 U8.1(AVDD) ; off-sheet BS_AMC
CLK_PhC: U8.7(CLKIN) ; off-sheet CLK_PhC
DAT_PhC: C62.1 R40.1 ; off-sheet DAT_PhC
DC_BUS_I: R33.2 TP2.1 U7.2(OUT) ; off-sheet DC_BUS_I
DCBUS: C46.1 R20.1 R22.2 ; off-sheet DCBUS
IA: U4.5(OUT) ; off-sheet IA
IB: U6.5(OUT) ; off-sheet IB
nOC: C64.1 R43.1 R44.2 ; off-sheet nOC
VA: C44.1 R19.1 R21.2 ; off-sheet VA
VB: C52.1 R27.1 R29.2 ; off-sheet VB
VC: C63.1 R42.1 R46.2 ; off-sheet VC
VC-MOTOR: R39.2 R42.2 R45.2 ; off-sheet VC-MOTOR
VREF: R25.1 R28.2 R32.2 ; off-sheet VREF
NetC45_2: C45.2 L1.2 U4.6(Vs)
NetC47_1: C47.1 R23.1 U4.1(IN-)
NetC47_2: C47.2 R24.1 U4.8(IN+)
NetC48_2: C48.2 R25.2 U4.7(REF1)
NetC49_2: C49.2 L3.2 U6.6(Vs)
NetC50_1: C50.1 L2.1 U5.1(IN)
NetC51_2: C51.2 R28.1 U5.2(OUT)
NetC53_1: C53.1 R31.1 U6.1(IN-)
NetC53_2: C53.2 R30.1 U6.8(IN+)
NetC54_2: C54.2 R32.1 U6.7(REF1)
NetC58_1: C58.1 C59.1 R37.1 U8.8(DVDD)
NetC60_1: C60.1 R35.1 U7.7(IN-)
NetC60_2: C60.2 R36.1 U7.8(IN+)
NetC61_1: C61.1 C66.1 R41.1 U8.2(INP)
NetC61_2: C61.2 C65.1 R45.1 U8.3(INN)
NetD1_1: D1.1(K) R34.2
NetJ9_1: J9.1 R79.2 U7.5(~{RESET})
NetR33_1: R33.1 R38.1 U7.3(CMPin)
NetR40_2: R40.2 U8.6(DOUT)
NetR44_1: R44.1 U14.4(Y)
NetR70_1: R70.1 U7.6(CMPout) U14.2(A)

Not connected (* = marked no-connect by the designer): U14 1(NC)

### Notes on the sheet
- (near R18) Phase A current sensing
- (near R18) Shunt: 1mΩ
  Gain:50
  Current range: ±33A
  Power: 0.4W@20A
- DC bus voltage sensing
- 80V (abs max) scaled to 3.3V
- Reference voltage
- (near R26) Phase B current sensing
- Shunt: 1mΩ
  Gain:50
  Current range: ±33A
  Power: 0.4W@20A
- (near TP2) Overcurrent protection
- ⬅
- Sets I_threshold to 30A
  Shunt: 1mΩ
  Gain:50
  R33 =16.5k
  R38 =11k
- Bootstrap from LMG2100 (default option)
- Phase C current sensing
- (near U8) Functional isolation
- Alternate bootstrap supply option for AMC0106M05
- (near R39) Shunt: 1mΩ
  V_IN: ±50mV/64mV
  Current range: ±50A/64A
- (near J9) Reset OCP

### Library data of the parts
C44 C46 C52 C63 = CMP-0006632-2: CAP, CERM, 0.033 uF, 10 V, +/- 10%, X7R, 0402; PartNumber: GRM155R71A333KA01D; Manufacturer: MuRata; Polarized: N; U/M: EA; Cap_F: 33nF; Value1: Unknown; VDC_V: 10V; TaMin_C: -55°C; TaMax_C: 125°C; AEC Category: Q200; SizeArea_mm2: 0.5; SizeAreaWB_mm2: 3; SizeX_mm: 1; SizeZ_mm: 0.6
C45 C49 C55 C56 C59 C93 = CMP-0006351-2: as C12 on sheet TIDA010936_GaN
C47 C53 C60 = CMP-0006245-2: CAP, CERM, 1500 pF, 25 V, +/- 5%, C0G/NP0, 0402; PartNumber: C0402H152J3GAC7867; Manufacturer: Kemet; Polarized: N; Value: 1500pF; U/M: EA; Cap_F: 1.5nF; Value1: Unknown; VDC_V: 25V; TaMin_C: -55°C; TaMax_C: 200°C; AEC Category: Q200; SizeArea_mm2: 0.5; SizeAreaWB_mm2: 3; SizeX_mm: 1; SizeZ_mm: 0.6
C48 C51 C54 = CMP-0007378-5: CAP, CERM, 0.1 uF, 16 V, +/- 10%, X7R, 0603; PartNumber: GRM188R71C104KA01D; Manufacturer: MuRata; Polarized: N; Value: 0.1uF; U/M: EA; Cap_F: 100nF; Value1: Unknown; VDC_V: 16V; TaMin_C: -55°C; TaMax_C: 125°C; SizeAreaWB_mm2: 4.68; SizeZ_mm: 1; SizeX_mm: 1.6; SizeY_mm: 0.8; SizeArea_mm2: 1.28; AEC Category: Q200
C50 = CMP-0007317-5: CAP, CERM, 1 uF, 10 V, +/- 10%, X5R, 0603; Manufacturer: MuRata; TaMin_C: -55°C; Polarized: N; SizeAreaWB_mm2: 4.68; Value1: Unknown; U/M: EA; Value: 1uF; TaMax_C: 85°C; SizeZ_mm: 1; SizeX_mm: 1.6; SizeY_mm: 0.8; SizeArea_mm2: 1.28; Cap_F: 1µF; AEC Category: Q200
C57 = CMP-0006527-2: as C40 on sheet TIDA010936_GaN
C58 = CMP-0006594-2: CAP, CERM, 2.2 uF, 16 V, +/- 10%, X5R, 0402; Manufacturer: MuRata; TaMin_C: -55°C; Polarized: N; SizeAreaWB_mm2: 3; Value1: Unknown; U/M: EA; Value: 2.2uF; TaMax_C: 85°C; SizeZ_mm: 0.6; SizeX_mm: 1; SizeY_mm: 0.5; Cap_F: 2.2µF; AEC Category: Q200
C61 = CMP-0006828-4: CAP, CERM, 0.01 uF, 16 V, +/- 10%, X7R, 0603; Manufacturer: Wurth Elektronik; TaMin_C: -55°C; Polarized: N; SizeAreaWB_mm2: 4.68; Value1: Unknown; U/M: EA; Value: 0.01uF; TaMax_C: 125°C; SizeZ_mm: 1; SizeX_mm: 1.6; SizeY_mm: 0.8; SizeArea_mm2: 1.28; AEC Category: Q200
C62 = CMP-0006919-4: CAP, CERM, 33 pF, 50 V, +/- 5%, C0G/NP0, 0603; Manufacturer: Kemet; TaMin_C: -55°C; Polarized: N; SizeAreaWB_mm2: 4.68; Value1: Unknown; U/M: EA; Value: 33pF; TaMax_C: 125°C; SizeZ_mm: 1; SizeX_mm: 1.6; SizeY_mm: 0.8; SizeArea_mm2: 1.28; AEC Category: Q200
C64 = CMP-0080092-1: CAP, CERM, 1000 pF, 25 V,+/- 1%, C0G/NP0, 0603; Manufacturer: Kemet; Cap_F: 1nF; SizeAreaWB_mm2: 4.68; SizeArea_mm2: 1.28; AEC Qualified: N; AEC Category: Q200; Value: 1000pF; TaMax_C: 125°C; SizeZ_mm: 1; Green_REACh: Passed; TaMin_C: -55°C; SizeY_mm: 0.8; Green_Lifecycle: Active; U/M: EA; SizeX_mm: 1.6
C65 C66 = CMP-0006723-2: CAP, CERM, 1000 pF, 100 V, +/- 5%, X7R, 0603; Manufacturer: AVX; TaMin_C: -55°C; ESR_ohm: 0.276; Polarized: N; SizeAreaWB_mm2: 4.68; Value1: 0.276 ohm; U/M: EA; Value: 1000pF; TaMax_C: 125°C; SizeZ_mm: 1; SizeX_mm: 1.6; SizeY_mm: 0.8; SizeArea_mm2: 1.28; AEC Category: Q200
D1 = CMP-0029023-2: Diode, Superfast Rectifier, 150 V, 1 A, SMA; Manufacturer: Diodes Inc.; TJmax_C: 150°C; Vr_V: 150V; Value2: 0.92V; SizeX_mm: 5.59; Green_REACh: Incomplete; SizeAreaWB_mm2: 37.3428; Value: 150V; Vf_V: 920mV; Green_Lifecycle: Not Set; Value1: 1A; SizeZ_mm: 2.87; SizeArea_mm2: 16.3228; SizeY_mm: 2.92; AEC Category: Q101; RJC_CperW: 25
J9 = CMP-0002337-1: as J1 on sheet TIDA010936_GaN
L1-L3 = CMP-0003227-1: Ferrite Bead, 300 ohm @ 100 MHz, 0.2 A, 0402; PartNumber: 74279272; Manufacturer: Wurth Elektronik; Imax_A: 200mA; DCR_ohm: 0.8; Value1: 0.8 ohm; Value2: 0.2A; ZTyp@100MHz_Ohm: 300; Ztyp@1GHz_Ohm: 316.308; SizeAreaWB_mm2: 3; SizeZ_mm: 0.6; SizeX_mm: 1; SizeY_mm: 0.5
R18 R26 R39 = CMP-0042666-1: as R1 on sheet TIDA010936_GaN
R19 R20 R27 R42 = CMP-0025950-3: RES, 100 k, 1%, 0.063 W, AEC-Q200 Grade 0, 0402; PartNumber: CRCW0402100KFKED; Manufacturer: Vishay-Dale; Value: 100k; Power_W: 63mW; Value2: 0.063W; VDC_V: 50V; TempCo: 100 ppm/C; EIA_Code: E96; AEC Category: Q200; AEC Qualified: Y; AEC Grade: 0; SizeArea_mm2: 0.5; SizeX_mm: 1; SizeZ_mm: 0.6
R21 R22 R29 R46 = CMP-0026407-2: RES, 4.22 k, 1%, 0.063 W, AEC-Q200 Grade 0, 0402; PartNumber: CRCW04024K22FKED; Manufacturer: Vishay-Dale; Value: 4.22k; Value_Code: 4k22; Power_W: 63mW; Value2: 0.063W; VDC_V: 50V; TempCo: 100 ppm/C; EIA_Code: E96; AEC Category: Q200; AEC Qualified: Y; AEC Grade: 0; SizeArea_mm2: 0.5; SizeX_mm: 1; SizeZ_mm: 0.6
R23 R24 R30 R31 R35-R37 = CMP-0026822-3: as R3 on sheet TIDA010936_GaN
R25 R28 R32 = CMP-0026822-3: RES, 0, 5%, 0.063 W, AEC-Q200 Grade 0, 0402; PartNumber: CRCW04020000Z0ED; Manufacturer: Vishay-Dale; Value: 0; Value_Code: 0000; Power_W: 63mW; Value2: 0.063W; VDC_V: 50V; TempCo: 200 ppm/C; EIA_Code: E24; SizeX_mm: 1; SizeY_mm: 0.5; SizeZ_mm: 0.6; AEC Qualified: Y; AEC Category: Q200
R33 = CMP-0026041-3: RES, 16.5 k, 1%, 0.063 W, AEC-Q200 Grade 0, 0402; Manufacturer: Vishay-Dale; Power_W: 63mW; TempCo: 100 ppm/C; Value_Code: 16k5; Value: 16.5k; EIA_Code: E96; SizeX_mm: 1; SizeY_mm: 0.5; SizeZ_mm: 0.6; Value2: 0.063W; AEC Qualified: Y; VDC_V: 50V; AEC Category: Q200; AEC Grade: 0
R34 = CMP-0096630-1: RES Thick Film, 3Ω, 1%, 0.33W, 100ppm/°C, 0603; Manufacturer: Vishay; AEC Grade: Grade 0; VDC_V: 75V; AEC Qualified: Yes; Power_W: 330mW; SizeZ_mm: 0.55mm; Power: 250mW
R38 = CMP-0093921-1: 11 kOhms ±1% 0.063W, 1/16W Chip Resistor 0402 (1005 Metric) Automotive AEC-Q200 Thick Film; Manufacturer: Stackpole; VDC_V: 50V; AEC Qualified: Yes; SizeZ_mm: 0.4mm; AEC Grade: Grade 0; TempCo: 100ppm/°C; Power_W: 63mW
R40 = CMP-0022479-4: RES, 50, 1%, 0.1 W, AEC-Q200 Grade 0, 0603; Manufacturer: Vishay-Dale; Power_W: 100mW; TempCo: 100 ppm/C; Value_Code: 50R0; Value: 50; SizeX_mm: 1.6; SizeY_mm: 0.8; SizeZ_mm: 1; Value2: 0.1W; SizeArea_mm2: 1.28; AEC Qualified: Y; VDC_V: 75V; AEC Category: Q200; AEC Grade: 0
R41 R45 = CMP-0022004-2: RES, 10.0, 1%, 0.25 W, 0603; Manufacturer: Vishay-Dale; Power_W: 250mW; TempCo: 100 ppm/C; Value_Code: 10R0; U/M: EA; Value: 10.0; EIA_Code: E96; Res_ohm: 10; SizeX_mm: 1.6; SizeY_mm: 0.8; SizeZ_mm: 1; Value2: 0.25W; SizeArea_mm2: 1.28; VDC_V: 75V; AEC Category: Q200
R43 R70 R79 = CMP-0026825-5: as R12 on sheet TIDA010936_GaN
R44 = CMP-0025899-5: RES, 1.0 k, 5%, 0.1 W, 0603; Manufacturer: Yageo; Power_W: 100mW; TempCo: 100 ppm/C; Value_Code: 1k00; Value: 1.0k; EIA_Code: E24; Res_ohm: 1k; SizeX_mm: 1.6; SizeY_mm: 0.8; SizeZ_mm: 1; Value2: 0.1W; SizeArea_mm2: 1.28; AEC Qualified: N; VDC_V: 75V; AEC Category: Q200; SizeAreaWB_mm2: 4.68
TP2 = CMP-0055137-1: as TP1 on sheet TIDA010936_GaN
TP3 = CMP-0055138-2: Test Point, Miniature, Black, TH; Manufacturer: Keystone Electronics; ContactFinish: Silver; CNHeader: FALSE; Green_Lifecycle: Active; Green_REACh: Passed; CT: TRUE
U4 U6 = CMP-0093649-2: -4-V to 110-V, Bidirectional, Ultra-Precise Current Sense Amplifier With Enhanced PWM Rejection; Manufacturer: Texas Instruments; Input Offset Voltage: 0.002mV; TaMax_C: +125°C; CompType: IC; Bandwidth: 1MHz; AEC Category: Q200; Response Time: 1.5us; TaMin_C: -40°C; Nominal Supply Current: 2.5mA; Number Of Channels: 1; TJmax_C: +150°C; Standoff Height: 0mm; SizeZ_mm: 1.1mm; Min Supply Voltage: 2.7V; Input Bias Current: 40uA; Voltage Gain: 0.05V/mV; AEC Qualified: No; Max Supply Voltage: 20V
U5 = CMP-0032556-1: 30 ppm / degC Drift, 3.9 uA Voltage Reference, -40 to 125 degC, 3-pin SOT-23 (DBZ), Green (RoHS & no Sb/Br); Manufacturer: Texas Instruments; Initial Accuracy @ 25/deg C(%): 0.15; Iout/Iz(Max)(mA): 5; Rating: Catalog; SubFamily: Series Voltage Reference; Temp Coeff(Max)(ppm/ degree C): 30; Temp Coeff(Typ)(ppm/ degree C): 8; VI(Max)(V): 5.5; VI(Min)(V): 3.5; VO(V): 3.3
U7 = CMP-0095220-1: -4V to 110V, 1.3-MHz, Ultra-Precise Current Sense Amplifier With OpenDrain Comparator and Reference; Manufacturer: Texas Instruments; Number Of Channels: 1; Nominal Supply Current: 1.5mA; Max Supply Voltage: 20V; Bandwidth: 1300kHz; Response Time: 10us; Min Supply Voltage: 2.7V; Input Bias Current: 20uA; TaMin_C: -40°C; Standoff Height: 0.05mm; TJmax_C: +150°C; TaMax_C: +125°C; SizeZ_mm: 1.1mm; AEC Qualified: No; Voltage Gain: 0.05V/mV; Input Offset Voltage: 0.015mV
U8 = CMP-0049066-2: ±50 mV Input Functionally Isolated Delta-Sigma Modulator for Current Sensing, VSON8; Manufacturer: Texas Instruments; Part Number: AMC0106DENR; SizeZ_mm: 1mm; Interface: SPI; Standoff Height: 0mm; AEC Category: Q200; CompType: IC
U14 = CMP-0859-00032-5: IC INVERTER SCHMITT 1CH SOT23-5; Manufacturer: Texas Instruments; Number Of Outputs: 1; Standoff Height: 0mm; Max Supply Voltage: 5.5V; Min Supply Voltage: 1.65V; Nominal Supply Current: 10uA; Max Junction Temp: +150°C; Logic Function Desc: Inverting; Propagation Delay: 6ns

## Sheet TIDA010936_Interface.SchDoc
size 431 x 279 mm; Date: Not shown in title block; ApprovedBy: Not shown in title block; CheckedBy: Not shown in title block; Author: Not shown in title block; CompanyName: Not shown in title block; Engineer: Not shown in title block; Organization: Not shown in title block; Address1: Not shown in title block; Address2: Not shown in title block; Address3: Not shown in title block; Address4: Not shown in title block; DocumentNumber: 2; Revision: Use project parameter SCH_Rev; SheetNumber: 2; SheetTotal: 3; PageSetup: Record=PageOptions¦CenterHorizontal=True¦CenterVertical=True¦PrintScale=1.00¦XCorrection=1.00¦YCorrection=1.00¦PrintKind=0¦BorderSize=5000000¦LeftOffset=0¦BottomOffset=0¦Orientation=2¦PaperLength=1000¦PaperWidth=1000¦Scale=100¦PaperSource=15¦PrintQuality=600¦MediaType=1¦DitherType=10¦PaperKind=Letter¦PrintScaleMode=1
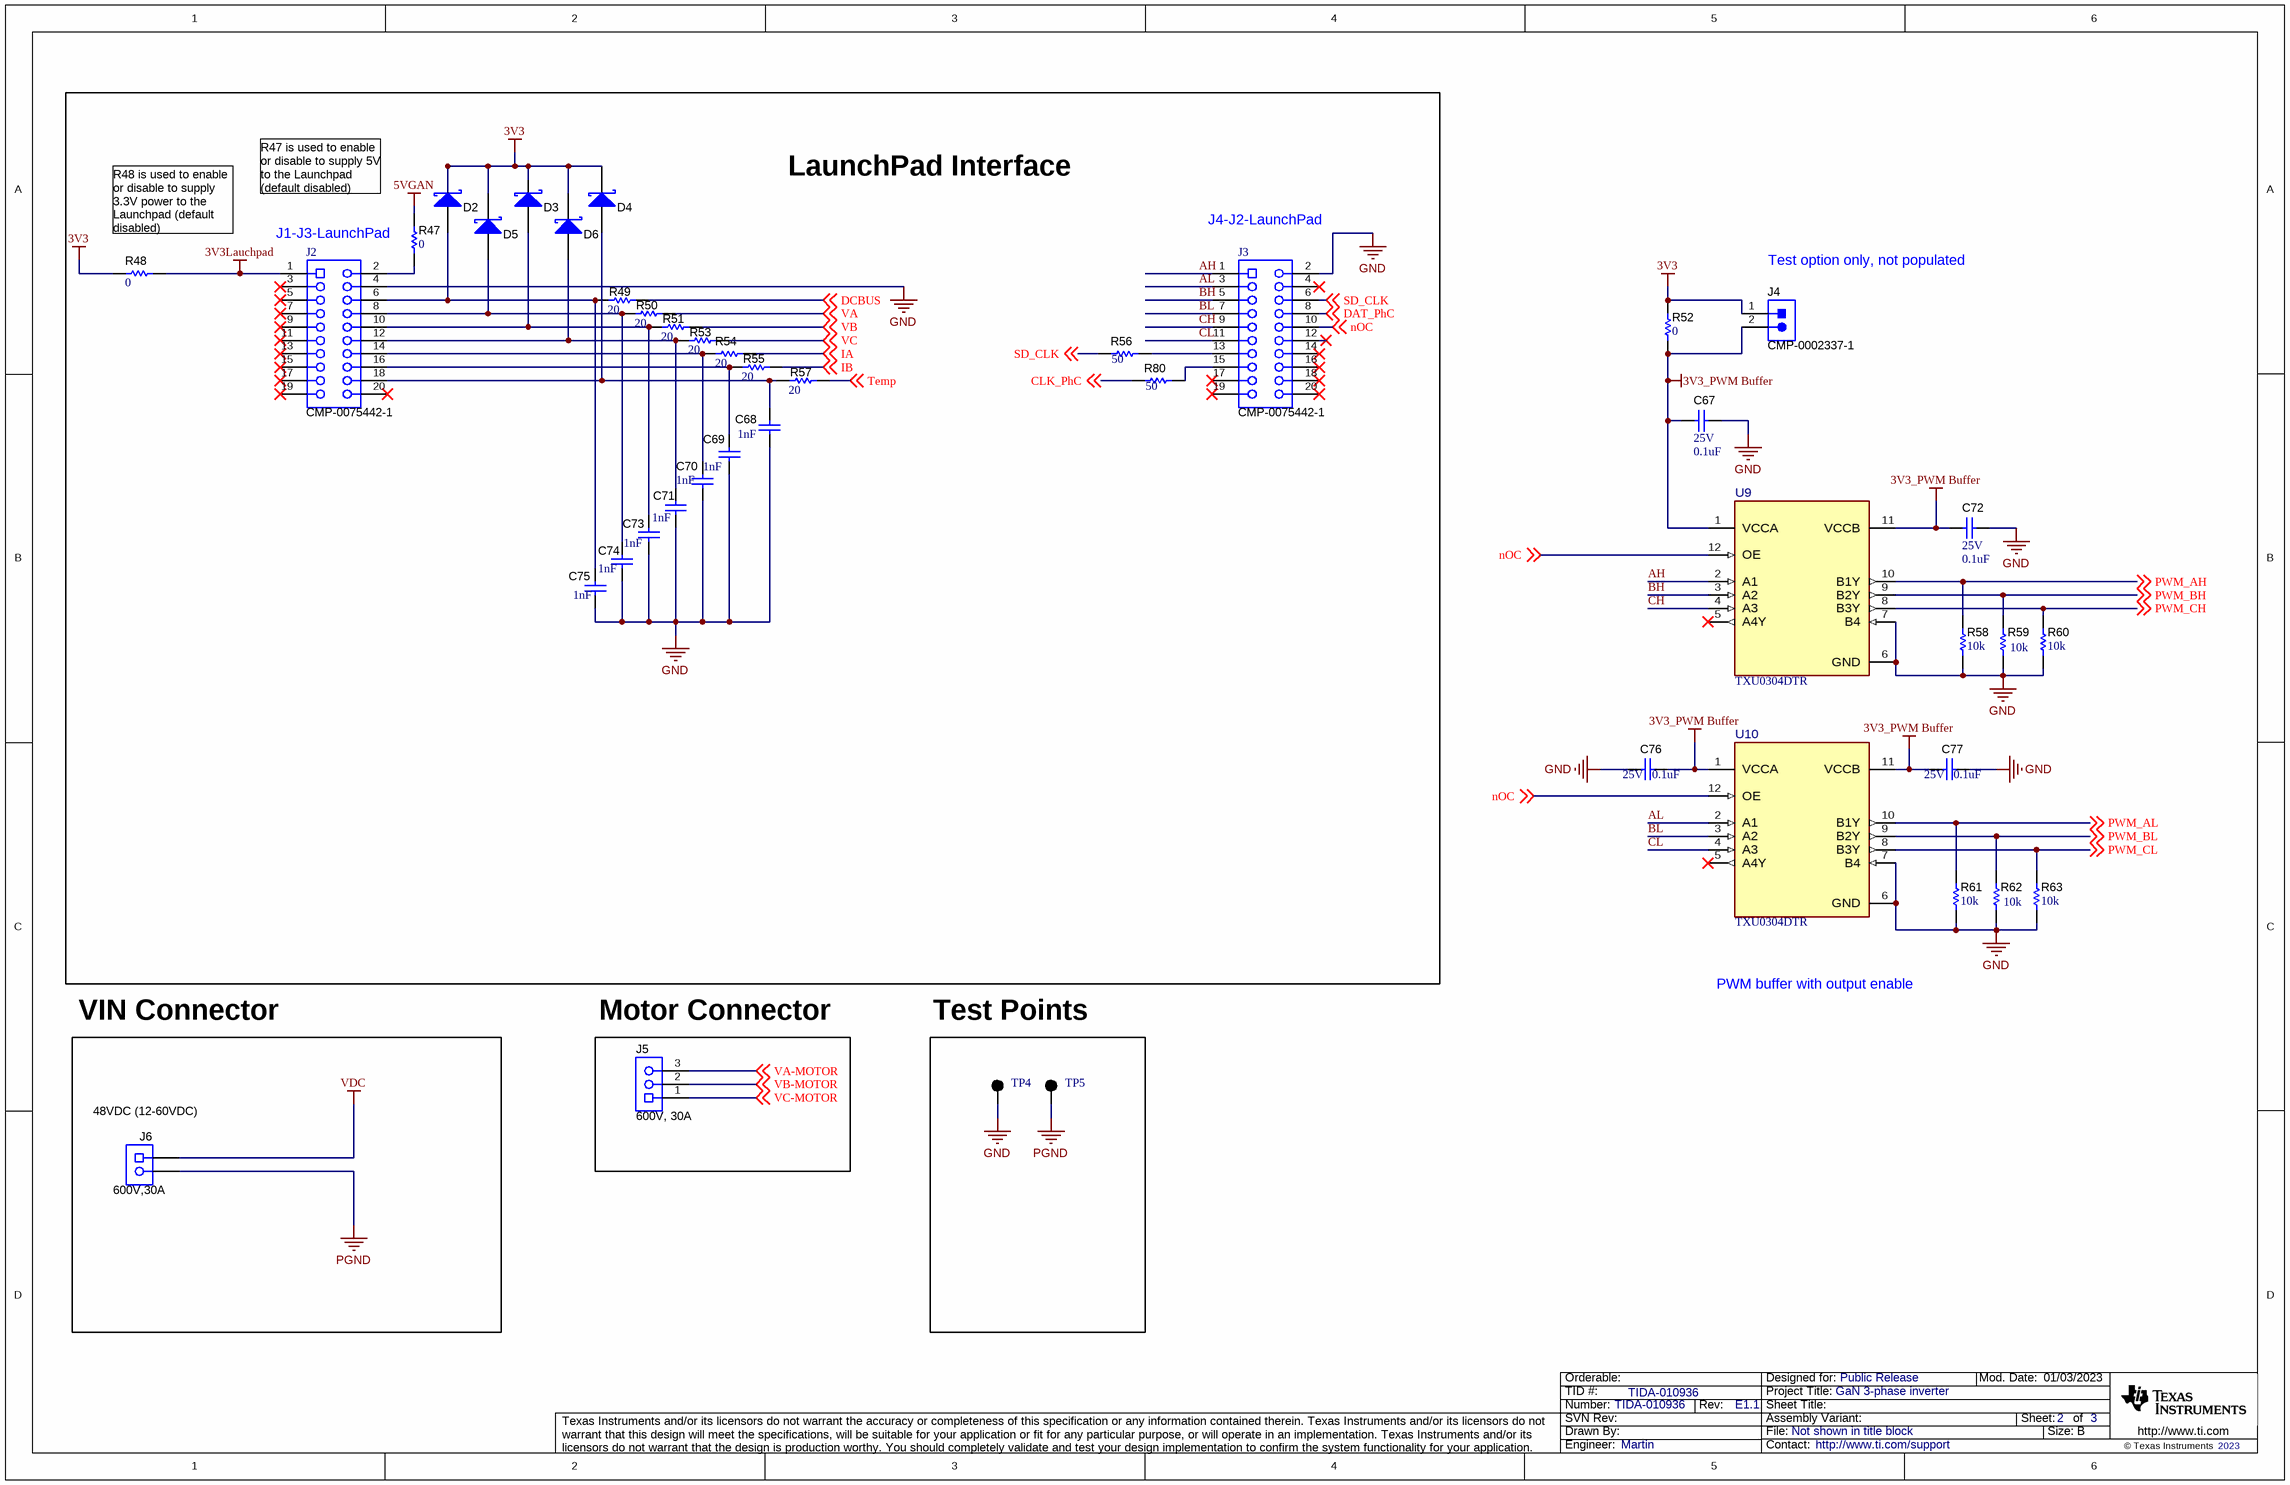
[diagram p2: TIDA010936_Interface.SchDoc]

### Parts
C67  VDC_V: 25V  ValueDisplayed: 0.1uF  [0402]  (hidden comment: GRM155R71E104KE14D)
C68  Cap_F: 1nF  [0603]  (hidden comment: 06031C102JAT2A)
C69  Cap_F: 1nF  [0603]  (hidden comment: 06031C102JAT2A)
C70  Cap_F: 1nF  [0603]  (hidden comment: 06031C102JAT2A)
C71  Cap_F: 1nF  [0603]  (hidden comment: 06031C102JAT2A)
C72  VDC_V: 25V  ValueDisplayed: 0.1uF  [0402]  (hidden comment: GRM155R71E104KE14D)
C73  Cap_F: 1nF  [0603]  (hidden comment: 06031C102JAT2A)
C74  Cap_F: 1nF  [0603]  (hidden comment: 06031C102JAT2A)
C75  Cap_F: 1nF  [0603]  (hidden comment: 06031C102JAT2A)
C76  VDC_V: 25V  ValueDisplayed: 0.1uF  [0402]  (hidden comment: GRM155R71E104KE14D)
C77  VDC_V: 25V  ValueDisplayed: 0.1uF  [0402]  (hidden comment: GRM155R71E104KE14D)
D2  CMP-0028644-3  [SOD-523]  (value not drawn)
D3  CMP-0028644-3  [SOD-523]  (value not drawn)
D4  CMP-0028644-3  [SOD-523]  (value not drawn)
D5  CMP-0028644-3  [SOD-523]  (value not drawn)
D6  CMP-0028644-3  [SOD-523]  (value not drawn)
J2  CMP-0075442-1  [CONN_SSW-110-23-F-D]
J3  CMP-0075442-1  [CONN_SSW-110-23-F-D]
J4  CMP-0002337-1  [CONN_PEC02SAAN]
J5  600V, 30A  [Phoenix_1904150]
J6  600V,30A  [Phoenix_1902547]
R47  ValueDisplayed: 0  [0603]  (hidden comment: PMR03EZPJ000)
R48  ValueDisplayed: 0  [0603]  (hidden comment: PMR03EZPJ000)
R49  ValueDisplayed: 20  [0402]  (hidden comment: CMP-0026876-3)
R50  ValueDisplayed: 20  [0402]  (hidden comment: CMP-0026876-3)
R51  ValueDisplayed: 20  [0402]  (hidden comment: CMP-0026876-3)
R52  ValueDisplayed: 0  [0402]  (hidden comment: CMP-0026822-3)
R53  ValueDisplayed: 20  [0402]  (hidden comment: CMP-0026876-3)
R54  ValueDisplayed: 20  [0402]  (hidden comment: CMP-0026876-3)
R55  ValueDisplayed: 20  [0402]  (hidden comment: CMP-0026876-3)
R56  ValueDisplayed: 50  [0603]  (hidden comment: CRCW060350R0FKEA)
R57  ValueDisplayed: 20  [0402]  (hidden comment: CMP-0026876-3)
R58  ValueDisplayed: 10k  [0402]  (hidden comment: CMP-0026825-5)
R59  ValueDisplayed: 10k  [0402]  (hidden comment: CMP-0026825-5)
R60  ValueDisplayed: 10k  [0402]  (hidden comment: CMP-0026825-5)
R61  ValueDisplayed: 10k  [0402]  (hidden comment: CMP-0026825-5)
R62  ValueDisplayed: 10k  [0402]  (hidden comment: CMP-0026825-5)
R63  ValueDisplayed: 10k  [0402]  (hidden comment: CMP-0026825-5)
R80  ValueDisplayed: 50  [0603]  (hidden comment: CRCW060350R0FKEA)
TP4  CMP-0055138-2  [Keystone5001]  (value not drawn)
TP5  CMP-0055138-2  [Keystone5001]  (value not drawn)
U9  TXU0304DTR  [DTR0012A-MFG]
U10  TXU0304DTR  [DTR0012A-MFG]

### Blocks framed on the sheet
LaunchPad Interface: C68-C71 C73-C75 D2-D6 J2 J3 R47-R51 R53-R57 R80
48VDC (12-60VDC): J6

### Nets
3V3: D2.1(K) D3.1(K) D4.1(K) D5.1(K) D6.1(K) J4.1 R48.2 R52.2
3V3_PWM Buffer: C67.1 C72.1 C76.2 C77.1 J4.2 R52.1 U9.1(VCCA) U9.11(VCCB) U10.1(VCCA) U10.11(VCCB)
3V3Lauchpad: J2.1 R48.1
5VGAN: R47.1
GND: C67.2 C68.2 C69.2 C70.2 C71.2 C72.2 C73.2 C74.2 C75.2 C76.1 C77.2 J2.4 J3.2 R58.1 R59.1 R60.1 R61.1 R62.1 R63.1 TP4.1 U9.6(GND) U9.7(B4) U10.6(GND) U10.7(B4)
PGND: J6.2 TP5.1
VA-MOTOR: J5.3 ; off-sheet VA-MOTOR  [project net AIN-]
VB-MOTOR: J5.2 ; off-sheet VB-MOTOR  [project net BIN-]
VDC: J6.1
AH: J3.1 U9.2(A1)
AL: J3.3 U10.2(A1)
BH: J3.5 U9.3(A2)
BL: J3.7 U10.3(A2)
CH: J3.9 U9.4(A3)
CL: J3.11 U10.4(A3)
CLK_PhC: R80.1 ; off-sheet CLK_PhC
DAT_PhC: J3.8 ; off-sheet DAT_PhC
DCBUS: R49.1 ; off-sheet DCBUS
IA: R54.1 ; off-sheet IA
IB: R55.1 ; off-sheet IB
nOC: J3.10 U9.12(OE) U10.12(OE) ; off-sheet nOC
PWM_AH: R58.2 U9.10(B1Y) ; off-sheet PWM_AH
PWM_AL: R61.2 U10.10(B1Y) ; off-sheet PWM_AL
PWM_BH: R59.2 U9.9(B2Y) ; off-sheet PWM_BH
PWM_BL: R62.2 U10.9(B2Y) ; off-sheet PWM_BL
PWM_CH: R60.2 U9.8(B3Y) ; off-sheet PWM_CH
PWM_CL: R63.2 U10.8(B3Y) ; off-sheet PWM_CL
SD_CLK: J3.6 R56.1 ; off-sheet SD_CLK
Temp: R57.1 ; off-sheet Temp
VA: R50.1 ; off-sheet VA
VB: R51.1 ; off-sheet VB
VC: R53.1 ; off-sheet VC
VC-MOTOR: J5.1 ; off-sheet VC-MOTOR
NetC68_1: C68.1 D4.2(A) J2.18 R57.2
NetC69_1: C69.1 J2.16 R55.2
NetC70_1: C70.1 J2.14 R54.2
NetC71_1: C71.1 D6.2(A) J2.12 R53.2
NetC73_1: C73.1 D3.2(A) J2.10 R51.2
NetC74_1: C74.1 D5.2(A) J2.8 R50.2
NetC75_1: C75.1 D2.2(A) J2.6 R49.2
NetJ2_2: J2.2 R47.2
NetJ3_13: J3.13 R56.2
NetJ3_15: J3.15 R80.2

Not connected (* = marked no-connect by the designer): J2 3* 5* 7* 9* 11* 13* 15* 17* 19* 20*; J3 4* 12* 14* 16* 17* 18* 19* 20*; U9 5(A4Y)*; U10 5(A4Y)*

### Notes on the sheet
- (near R48) R48 is used to enable or disable to supply 3.3V power to the Launchpad (default disabled)
- R47 is used to enable or disable to supply 5V to the Launchpad (default disabled)
- J1-J3-LaunchPad
- (near J3) J4-J2-LaunchPad
- (near J4) Test option only, not populated
- VIN Connector
- (near J5) Motor Connector
- Test Points
- PWM buffer with output enable

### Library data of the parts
C67 C72 C76 C77 = CMP-0006659-2: CAP, CERM, 0.1 uF, 25 V, +/- 10%, X7R, 0402; Manufacturer: MuRata; TaMin_C: -55°C; Polarized: N; SizeAreaWB_mm2: 3; Value1: Unknown; U/M: EA; Value: 0.1uF; TaMax_C: 125°C; SizeZ_mm: 0.6; SizeX_mm: 1; SizeY_mm: 0.5; Cap_F: 100nF; AEC Category: Q200
C68-C71 C73-C75 = CMP-0006723-2: CAP, CERM, 1000 pF, 100 V, +/- 5%, X7R, 0603; Manufacturer: AVX; TaMin_C: -55°C; ESR_ohm: 0.276; Polarized: N; SizeAreaWB_mm2: 4.68; Value1: 0.276 ohm; U/M: EA; Value: 1000pF; TaMax_C: 125°C; SizeZ_mm: 1; SizeX_mm: 1.6; SizeY_mm: 0.8; Value2: 100V; SizeArea_mm2: 1.28; AEC Category: Q200
D2-D6 = CMP-0028644-3: Diode, Schottky, 70 V, 0.07 A, SOD-523; PartNumber: 1PS79SB70,115; Manufacturer: Nexperia; Vf_V: 410mV; Value: 70V; Value1: 0.07A; Value2: 0.41V; Io_A: 70mA; TJmax_C: 150°C; SizeAreaWB_mm2: 5.13; SizeArea_mm2: 1.53; SizeX_mm: 1.7; SizeY_mm: 0.9; SizeZ_mm: 0.65; AEC Category: Q101; Green_Lifecycle: Not Set; Green_REACh: Incomplete
J2 J3 = CMP-0075442-1: Connector, Receptacle, 100mil, 10x2, Gold plated, TH; PartNumber: SSW-110-23-F-D; Manufacturer: Samtec; CompType: Socket Strip; Green_Lifecycle: Active; Green_REACh: Passed; CT: True; CNHeader: False
J4 = CMP-0002337-1: as J1 on sheet TIDA010936_GaN
J5 = CMP-0055528-1: Terminal Block, 9.52mm, 3x1, R/A, TH; Manufacturer: Phoenix Contact; PartNumber: 1904150; Cert_VDE: Y; CNHeader: FALSE; Current_A: 32A; Gender: Female; Voltage_V: 1kV; Row_Count: 1; Pitch_mm: 9.52; CT: TRUE
J6 = CMP-0055527-1: Terminal Block, 9.52mm, 2x1, R/A, TH; PartNumber: 1902547; Manufacturer: Phoenix Contact; Pitch_mm: 9.52; Gender: Female; Row_Count: 1; Current_A: 32A; Voltage_V: 1kV; Cert_UL: Y; CNHeader: FALSE; CT: TRUE
R47 R48 = CMP-0086358-1: RES, 0, 0%, 0.25 W, AEC-Q200 Grade 0, 0603; Manufacturer: Rohm; Power_W: 250mW; SizeZ_mm: 1; SizeArea_mm2: 1.28; Value2: 0.25W; SizeAreaWB_mm2: 4.68; Value_Code: 0000; Value: 0; AEC Qualified: Y; AEC Category: Q200; SizeX_mm: 1.6; SizeY_mm: 0.8
R49-R51 R53-R55 R57 = CMP-0026876-3: RES, 20, 5%, 0.063 W, AEC-Q200 Grade 0, 0402; PartNumber: CRCW040220R0JNED; Manufacturer: Vishay-Dale; Value: 20; Value_Code: 20R0; Power_W: 63mW; Value2: 0.063W; VDC_V: 50V; TempCo: 200 ppm/C; EIA_Code: E24; AEC Category: Q200; AEC Qualified: Y; AEC Grade: 0; SizeArea_mm2: 0.5; SizeX_mm: 1; SizeZ_mm: 0.6
R52 = CMP-0026822-3: as R3 on sheet TIDA010936_GaN
R56 R80 = CMP-0022479-4: as R40 on sheet TIDA010936_Current sensing
R58-R63 = CMP-0026825-5: as R12 on sheet TIDA010936_GaN
TP4 TP5 = CMP-0055138-2: as TP3 on sheet TIDA010936_Current sensing
U9 U10 = CMP-0091905-2: 4-Bit Fixed Direction Voltage-Level Translator with SchmittTrigger Inputs, and Tri-State Outputs; Manufacturer: Texas Instruments; AEC Category: Q200; Number Of Outputs: 4; PositionCount: 1; V B Min: 1.1V; V A Max: 5.5V; CompType: IC; SizeZ_mm: 0.4mm; Standoff Height: 0mm; Logic Function Desc: Non-Inverting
